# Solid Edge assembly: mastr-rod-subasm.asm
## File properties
Author: Deepak Maini
Template: Normal.asm
Last saved by: MYPC
Revision: 12
Application: Solid Edge
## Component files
master rod.par
piston.par
piston pin.par
piston pin plug.par
piston ring.par
master rod bearing.par
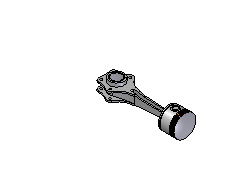
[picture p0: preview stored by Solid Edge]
